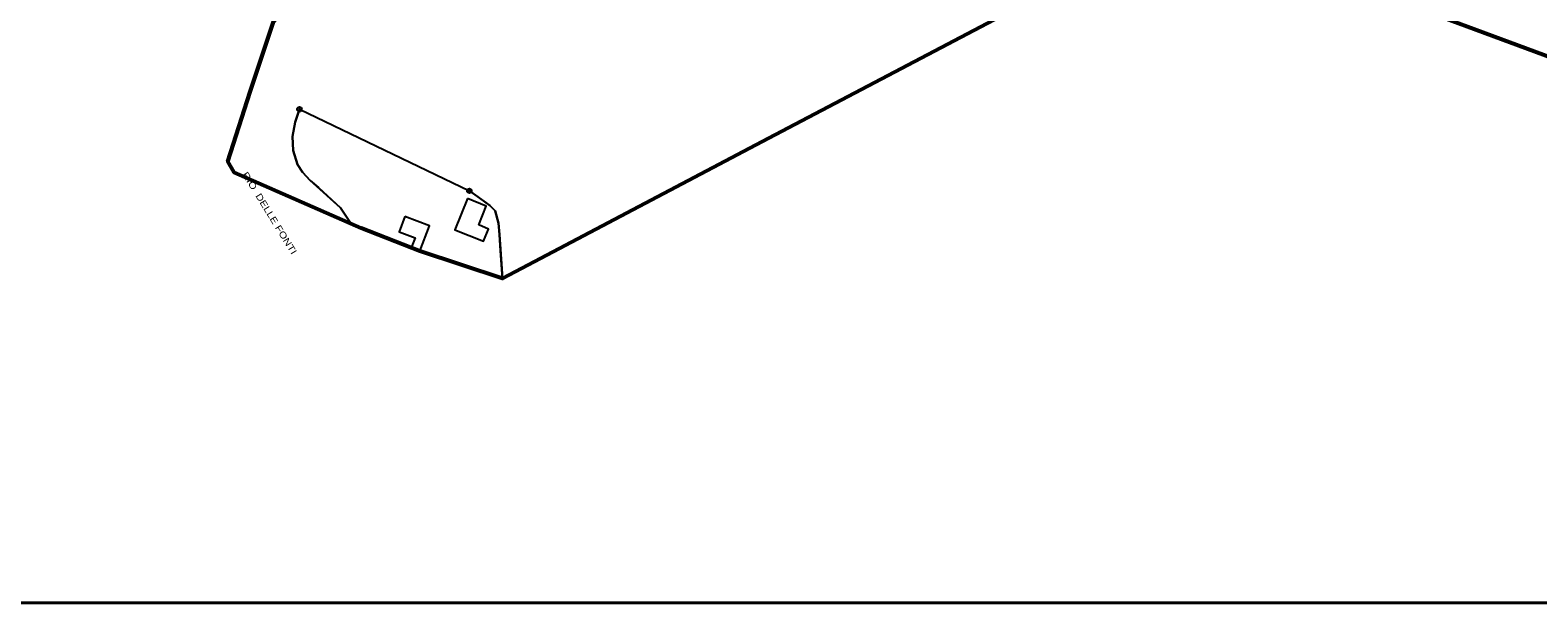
# Model space of a CAD drawing. Extents: x 654952 to 658955, y 890426 to 894481.
# Drawn here: x 657509 to 658161, y 890426 to 890674 of the extents above; entities that cross this region are included whole.
import ezdxf

# ---------------------------------------------------------------- set-up
doc = ezdxf.new("R2010")
doc.units = 0
doc.header["$LTSCALE"] = 4
doc.header["$PDMODE"] = 32
doc.header["$PDSIZE"] = 2
for name, color, linetype, lineweight in [('1', 7, 'Continuous', 25), ('35', 7, 'Continuous', 25), ('59', 7, 'Continuous', 53), ('60', 7, 'Continuous', 35)]:
    doc.layers.add(name, color=color, linetype=linetype, lineweight=lineweight)
doc.layers.add('58', color=7, linetype='Continuous')

msp = doc.modelspace()

# ---------------------------------------------------------------- linework, layer by layer
at = {"layer": '1'}
for points in [[(657625.62, 890639.42), (657623.74, 890633.85), (657622.56, 890627.58), (657622.97, 890621.63), (657624.81, 890615.59), (657626.89, 890612.16), (657630.27, 890608.55)], [(657630.27, 890608.55), (657633.92, 890605.55), (657643.32, 890596.83), (657648.27, 890589.36), (657652.32, 890587.93), (657663.99, 890583.34), (657677.18, 890578.63), (657687.78, 890575.06), (657701.9, 890570.27), (657713.55, 890566.25), (657712.68, 890578.22), (657712.16, 890585.26), (657711.8, 890590.19), (657710.32, 890595.43), (657708.07, 890597.82), (657703.61, 890600.98), (657699.14, 890604.14)]]:
    msp.add_lwpolyline(points, dxfattribs=at)
for points in [[(657698.28, 890600.76), (657692.91, 890587.29), (657705.23, 890582.39), (657707.48, 890587.52), (657703.24, 890589.45), (657706.45, 890597.5)], [(657671.29, 890593.09), (657668.75, 890586.46), (657675.66, 890583.81), (657673.99, 890579.46), (657677.67, 890578.03), (657681.93, 890588.99)]]:
    msp.add_lwpolyline(points, close=True, dxfattribs=at)
for p in [(657625.62, 890639.42), (657699.14, 890604.14)]:
    msp.add_point(p, dxfattribs=at)
at = {"layer": '35'}
for points in [[(657614.42, 890677.28), (657594.65, 890616.78), (657597.36, 890612.12), (657648.27, 890589.36), (657643.32, 890596.83), (657630.27, 890608.55), (657626.89, 890612.16), (657624.81, 890615.59), (657622.97, 890621.63), (657622.56, 890627.58), (657623.74, 890633.85), (657625.62, 890639.42), (657699.14, 890604.14), (657708.07, 890597.82), (657710.32, 890595.43), (657711.8, 890590.19), (657712.16, 890585.26), (657713.55, 890566.25), (657969.14, 890700.78)], [(658064.38, 890699.85), (658193.76, 890651.87)]]:
    msp.add_lwpolyline(points, dxfattribs=at)
at = {"layer": '59'}
msp.add_lwpolyline([(658193.76, 890651.87), (658064.38, 890699.85), (658064.38, 890699.85), (657974.41, 890701.09), (657969.14, 890700.78), (657969.14, 890700.78), (657825.69, 890625.28), (657729.93, 890574.87), (657713.55, 890566.25), (657677.67, 890578.03), (657652.32, 890587.93), (657597.36, 890612.12), (657594.65, 890616.78), (657604.34, 890647.03), (657614.42, 890677.28), (657617.13, 890680.77), (657584.57, 890724.6), (657567.52, 890749.43), (657558.34, 890772.82), (657526.68, 890791.63), (657492.71, 890827.78)], dxfattribs=at)
at = {"layer": '60', "lineweight": 40}
msp.add_lwpolyline([(657055.17, 894480.74), (658955.28, 894480.74), (658955.28, 890425.88), (657055.17, 890425.88)], close=True, dxfattribs=at)

# ---------------------------------------------------------------- texts
at = {"layer": '58', "width": 1.25}
msp.add_text('RIO  DELLE FONTI', height=2.799, rotation=301.649, dxfattribs=at).set_placement((657600.73, 890611.26))

doc.saveas('drawing.dxf')
